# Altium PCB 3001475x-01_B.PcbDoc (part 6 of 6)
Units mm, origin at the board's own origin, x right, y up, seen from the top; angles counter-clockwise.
Board outline 335 x 91 mm, 12 copper layers (Top Layer, L2 GND, Layer 3, L4 GND, Layer 5, L6 PWR, L7 3V3, Layer 8, L9 GND, Layer 10, L11 GND, Bottom Layer), stack 1.59 mm thick; 339 components, 431 nets, 1732 pads, 1526 vias.
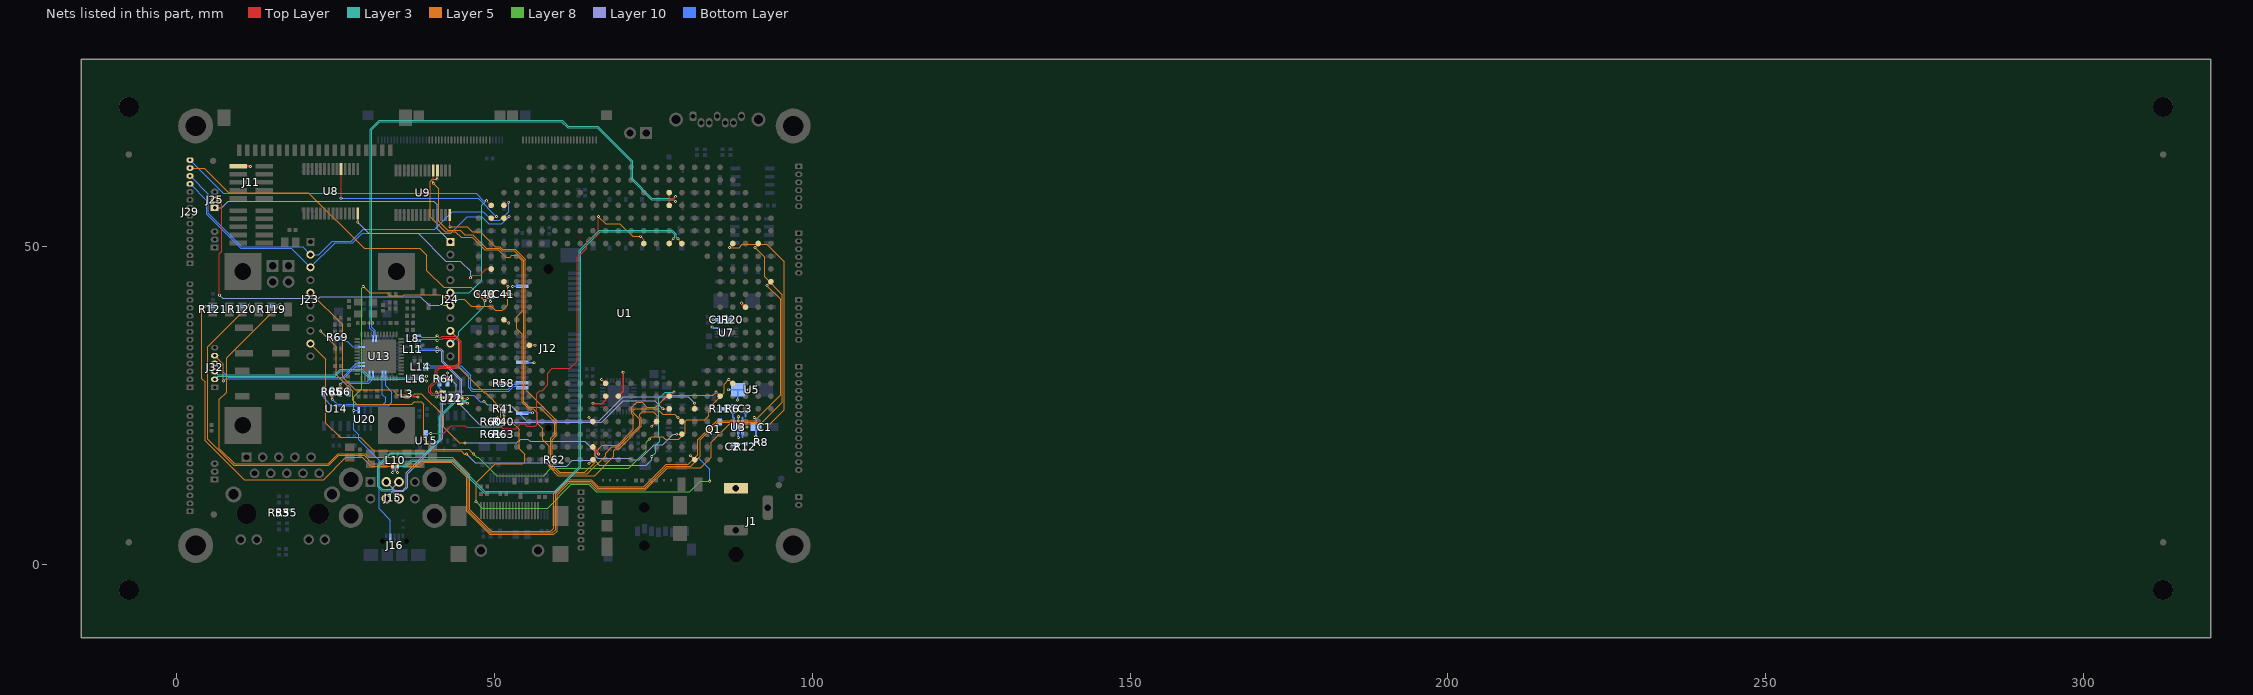
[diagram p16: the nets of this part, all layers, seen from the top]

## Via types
v1: diameter 0.45, hole 0.2, Top Layer to Bottom Layer, 1511 vias
v2: diameter 0.5, hole 0.2, Top Layer to Bottom Layer, 14 vias
v3: diameter 0.45/0.45/0.45/0.45/0.45/0.45/0.45/0.45/0.45/0.45/0.45/0.45 (per signal layer), hole 0.2, Top Layer to Bottom Layer, 1 vias

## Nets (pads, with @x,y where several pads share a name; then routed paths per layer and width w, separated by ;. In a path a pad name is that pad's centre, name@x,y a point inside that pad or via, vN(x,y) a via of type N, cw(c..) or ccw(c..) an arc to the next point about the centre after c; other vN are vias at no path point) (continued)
UART3_RTS_N: U1.AA15 U9.18 | length 88
  Top Layer w0.125: v1(41,60.625) U9.18@41,61.975 ; v1(74.75,21.75) U1.AA15@75.5,22.5
  Layer 5 w0.125: v1(41,60.625) 40.25,60.625 39.875,60.25 39.875,54.75 42.25,52.375 43.875,52.375 44.75,51.5 46.5,51.5 48.5,49.5 50.625,49.5 51.75,48.375 52.5,48.375 52.75,48.625 53.521,48.625 54.375,47.771 54.375,39.875 53.5,39 53.5,37.125 54.375,36.25 54.375,25.521 55.396,24.5 55.604,24.5 56.125,24.5 56.75,23.875 56.75,22.25 57.625,21.375 57.625,19.625 58.625,18.625 58.625,15.375 60,14 65.75,14 68.75,17 68.75,17.875 69.125,18.25 69.625,18.25 73.125,21.75 73.125,23 72.875,23.25 72.875,23.625 73.25,24 75,24 75.625,23.375 75.625,22.625 v1(74.75,21.75)
UART3_RX: U1.AA17 U9.19 | length 89.1
  Top Layer w0.125: v1(40.375,60) U9.19@40.375,62 ; v1(78.875,23.125) U1.AA17@79.5,22.5
  Layer 5 w0.125: v1(40.375,60) 41.25,59.125 41.25,54 42.625,52.625 44.625,52.625 45.375,51.875 46.625,51.875 48.75,49.75 50.75,49.75 51.125,49.375 53.125,49.375 54.625,47.875 54.625,25.625 55.5,24.75 57.125,24.75 59.5,22.375 59.5,20.5 58.875,19.875 58.875,15.5 60.125,14.25 64.625,14.25 67.5,17.125 67.5,17.5 68.5,18.5 69.5,18.5 72.875,21.875 72.875,22.875 71.875,23.875 71.875,24.25 72.125,24.5 75.625,24.5 76.5,23.625 78.375,23.625 v1(78.875,23.125)
UART3_TX: U1.W20 U9.14 | length 86.8
  Top Layer w0.125: U9.14@42.975,55 42.975,53.15 v1(43,53.125) ; U9.14@43,55 U9.14@43,55.025 ; v1(84.875,27.125) U1.W20@85.5,26.5
  Layer 5 w0.125: v1(43,53.125) 45.75,53.125 46.5,52.375 47.75,52.375 50.125,50 50.875,50 51.25,49.625 53.25,49.625 54.875,48 54.875,27.583 59.75,22.708 59.75,20.25 59.125,19.625 59.125,15.625 60.25,14.5 64.25,14.5 65.875,16.125 65.875,17.625 67,18.75 69.375,18.75 71.875,21.25 71.875,23.5 71.625,23.75 71.625,24.75 72.375,25.5 73.25,25.5 74,24.75 75.375,24.75 77.25,26.625 84.375,26.625 v1(84.875,27.125)
UART4_RX: U1.E2 U8.19 | length 31.1
  Top Layer w0.125: v1(25.875,57.625) U8.19@25.875,62.228 ; U1.E2@49.5,54.5 v1(50.325,54.75)
  Bottom Layer w0.125: v1(25.875,57.625) 47.45,57.625 v1(50.325,54.75)
UART4_TX: U1.J2 U8.14 | length 27.2
  Top Layer w0.125: v1(28.5,53.875) U8.14@28.5,55.247 ; v1(46.25,45.125) 46.625,45.5 47.75,45.5 48.75,46.5 U1.J2@49.5,46.5
  Layer 10 w0.125: v1(28.5,53.875) 30.25,52.125 38,52.125 42.375,47.75 44.625,47.75 46.25,46.125 v1(46.25,45.125)
UART5_CTS_N: J24.5 J29.14 U1.D2 | length 68.9
  Top Layer w0.125: v1(48.75,57.25) U1.D2@49.5,56.5
  Layer 3 w0.125: J24.5@43.072,42.758 46.008,42.758 48,44.75 48,56.5 v1(48.75,57.25)
  Bottom Layer w0.125: J29.14@2.125,63.625 7.375,58.375 47.125,58.375 48.25,57.25 v1(48.75,57.25)
UART5_RTS_N: J24.9 J29.13 U1.L2 | length 67.4
  Top Layer w0.125: v1(48.5,41.5) U1.L2@49.5,42.5
  Layer 5 w0.125: J29.13@2.125,62.375 4.375,62.375 8.25,58.5 20.75,58.5 29.5,49.75 38.25,49.75 39.375,48.625 39.375,46.25 42,43.625 46.375,43.625 v1(48.5,41.5)
  Layer 3 w0.125: J24.9@43.072,34.758 44.375,36.061 44.375,36.625 48.5,40.75 v1(48.5,41.5)
  Bottom Layer w0.125: 2,62.875 2,62.625 2.125,62.5 J29.13@2.125,62.375
UART5_RX: J23.2 J29.12 U1.D3 | length 63.3
  Top Layer w0.125: U1.D3@51.5,56.5 v1(52.25,57)
  Bottom Layer w0.125: J29.12@2.125,61.125 5,58.25 5,55.25 10.25,50 19.83,50 J23.2@21.072,48.758 22.367,48.758 24.5,50.891 27.516,50.891 29.375,52.75 40.625,52.75 43.375,55.5 48.25,55.5 49.625,54.125 50.875,54.125 52.25,55.5 v1(52.25,57)
UART5_TX: J23.3 J29.11 U1.E3 | length 61.9
  Top Layer w0.125: U1.E3@51.5,54.5 v1(52.3,54.75)
  Bottom Layer w0.125: J29.11@2.125,59.875 4.75,57.25 4.75,55.125 10.125,49.75 18.08,49.75 J23.3@21.072,46.758 24.939,50.625 27.75,50.625 29.25,52.125 43.125,52.125 45.75,54.75 48,54.75 49.125,53.625 51.175,53.625 v1(52.3,54.75)
USB_HUB_RESET_N: R69.2 U1.V21 U13.26 | length 99.4
  Top Layer w0.125: v1(86.875,29.125) U1.V21@87.5,28.5
  Layer 8 w0.125: v1(46.75,17.375) 47.25,16.875 47.5,16.875 50.375,14 57.771,14 58.896,15.125 71.125,15.125 73.875,17.875 73.875,19.25 v1(74.375,19.75)
  Layer 5 w0.125: v1(22.625,36.75) 25.125,34.25 25.125,29.875 27.75,27.25 27.75,25.875 28.375,25.25 37,25.25 37.375,25.625 38.5,25.625 38.875,25.25 38.875,19.75 40.5,18.125 46,18.125 v1(46.75,17.375) ; v1(74.375,19.75) 74.75,20.125 76.5,20.125 76.875,19.75 79,19.75 80,20.75 80,22.5 80.25,22.75 83.125,22.75 83.75,23.375 83.75,24.625 86.125,27 86.125,28.375 v1(86.875,29.125)
  Bottom Layer w0.125: v1(22.625,36.75) 24.25,35.125 25.25,35.125 25.855,35.73 R69.2@25.855,35.75 26.48,35.125 26.875,35.125 27.75,34.25 U13.26@29.075,34.25
USB_OTG_D_N: L10.1 U1.G16 | length 87
  Top Layer w0.155: v1(34.75,14.5) 34.75,14.923 34.775,14.948 L10.1@34.775,15.525 ; U1.G16@77.5,50.5 v1(78.125,51.25)
  Layer 3 w0.103: v1(34.75,14.5) 34.49,14.76 34.49,15.191 34.745,15.446 36.246,15.446 37.046,16.246 43.429,16.246 48.354,11.321 59.571,11.321 63.575,15.325 63.575,49.325 66.625,52.375 77.876,52.375 78.385,51.866 78.385,51.51 v1(78.125,51.25)
USB_OTG_D_P: L10.4 U1.G17 | length 87.8
  Top Layer w0.155: L10.4@33.975,15.525 33.975,14.948 34,14.923 v1(34,14.5) ; v1(78.875,51.25) U1.G17@79.5,50.5
  Layer 3 w0.103: v1(34,14.5) 34.261,14.76 34.261,15.285 34.65,15.675 36.151,15.675 36.951,16.475 43.524,16.475 48.449,11.55 59.476,11.55 63.346,15.42 63.346,49.42 66.53,52.604 77.971,52.604 78.615,51.96 78.615,51.51 v1(78.875,51.25)
USB_OTG_ID: J16.4 U1.K3 U20.1 | length 72
  Top Layer w0.125: U1.K3@51.5,44.5 v1(52.125,43.75)
  Layer 8 w0.125: v1(27.875,24.25) 27.875,26.375 29.125,27.625 29.125,43.5 v1(29.375,43.75)
  Layer 5 w0.125: v1(29.375,43.75) 30.375,42.75 33.125,42.75 33.625,42.25 35.625,42.25 35.788,42.413 41.837,42.413 42.5,41.75 45.25,41.75 46.375,40.625 49.5,40.625 50.125,40 51.25,40 52.125,40.875 v1(52.125,43.75)
  Bottom Layer w0.125: v1(27.875,24.25) 27.875,21.21 28.625,20.46 28.625,19.625 31.875,16.375 31.875,8.75 33.65,6.975 J16.4@33.65,4.15 ; v1@27.9,24.275 U20.1@28.675,24.275
USB_OTG_OC: R64.1 U1.Y16 U12.2 | length 44.3
  Top Layer w0.125: R64.1@42.625,29.27 v1(42.625,30.125) ; v1(76.5,24.5) U1.Y16@77.5,24.5
  Layer 10 w0.125: v1(42.625,30.125) 42.625,29.625 44,28.25 44,25.75 47.875,21.875 51.25,21.875 51.75,22.375 66.875,22.375 70.25,25.75 75.25,25.75 v1(76.5,24.5)
  Bottom Layer w0.125: U12.2@42.625,28.835 v1(42.625,30.125)
USB_OTG_PWR: U1.Y18 U12.1 | length 46.2
  Top Layer w0.125: U1.Y18@81.5,24.5 v1(81.5,25.375)
  Layer 10 w0.125: v1(48.375,25.625) 48.875,25.125 52.5,25.125 55,22.625 66.5,22.625 70.25,26.375 80.5,26.375 v1(81.5,25.375)
  Bottom Layer w0.125: U12.1@41.345,28.825 41.345,27.78 42.375,26.75 44.25,26.75 44.375,26.625 46.75,26.625 47.75,25.625 v1(48.375,25.625)
USB_OTG_VBUS: U1.G14 U15.D | length 67
  Top Layer w0.125: v1(40,20.625) 42,20.625 43.25,21.875 45.375,21.875 45.625,21.625 51.125,21.625 51.375,21.375 53.375,21.375 54.125,22.125 54.75,22.125 55.125,21.75 56.375,21.75 56.625,22 56.625,26.875 57.125,27.375 57.5,27.375 58.375,28.25 58.375,30.125 59.125,30.875 61.875,30.875 63,32 63,48.25 64.5,49.75 64.5,51 65,51.5 65.75,51.5 66.375,52.125 v1(66.375,54.75) ; v1(73,51.625) 73.5,51.125 U1.G14@73.5,50.5
  Layer 5 w0.125: v1(66.375,54.75) 67.5,53.625 69.75,53.625 71.75,51.625 v1(73,51.625)
  Bottom Layer w0.125: U15.D@39.275,20.625 v1(40,20.625)
USBH1_D_N: J15.A2 L8.2 U21.1 | length 43.3
  Top Layer w0.155: v1@40.757,27.125 v1(40.875,27.125) ; v1(41,36) 41.232,35.768 41.645,35.768 41.778,35.9 43.975,35.9 44.8,35.075 44.8,31.825 43.89,30.915 41.418,30.915 40.975,30.472 40.975,28.875 39.975,27.875 39.975,27.203 40.278,26.9 40.65,26.9 v1(40.875,27.125) ; U21.1@41.775,27.125 v1(40.875,27.125)
  Layer 10 w0.103: J15.A2@33,13 33.896,12.104 33.896,11.804 34.2,11.5 35.7,11.5 36.375,12.175 36.375,14.325 41.9,19.85 41.9,26.434 41.47,26.865 41.136,26.865 v1(40.875,27.125)
  Bottom Layer w0.155: L8.2@37.975,36.025 38.348,36.025 38.606,35.768 40.768,35.768 v1(41,36)
USBH1_D_P: J15.A3 L8.3 U21.2 | length 42
  Top Layer w0.155: v1(41,35.25) 41.232,35.482 41.763,35.482 41.896,35.615 43.857,35.615 44.515,34.957 44.515,31.943 43.772,31.2 41.3,31.2 40.69,30.59 40.69,28.993 39.69,27.993 39.69,27.085 40.16,26.615 40.635,26.615 v1(40.875,26.375) U21.2@41.725,26.375
  Layer 10 w0.103: J15.A3@35,13 34.125,12.125 34.125,11.899 34.295,11.729 35.605,11.729 36.146,12.27 36.146,14.42 41.671,19.945 41.671,26.34 41.375,26.635 41.136,26.635 v1(40.875,26.375)
  Bottom Layer w0.155: L8.3@37.975,35.225 38.325,35.225 38.583,35.482 40.768,35.482 v1(41,35.25)
USBH1_OC_N: R65.1 U13.13 U14.2 | length 15.3
  Top Layer w0.125: v1@24.49,26.01 R65.1@24.49,26.72
  Bottom Layer w0.125: v1@24.49,26.01 U14.2@24.49,27.2 ; v1(24.5,26) 25.25,25.25 32.5,25.25 32.875,25.625 32.875,26.25 32.375,26.75 U13.13@32.375,29.95
USBH1_PWR_EN: U13.12 U14.1 | length 17.2
  Bottom Layer w0.125: U14.1@23.22,27.2 23.22,26.155 24.375,25 33.375,25 33.875,25.5 33.875,27.125 32.875,28.125 U13.12@32.875,29.95
USBH2_D_N: J15.B2 L11.2 U21.5 | length 43
  Top Layer w0.155: U21.5@44.775,26.125 v1(45.75,26.125)
  Layer 10 w0.103: v1(41,34.125) 41.198,33.927 41.572,33.927 41.954,33.545 41.954,31.996 44.854,29.096 44.854,26.22 45.209,25.864 45.49,25.864 v1(45.75,26.125)
  Layer 3 w0.103: J15.B2@33,10.38 33.871,11.251 33.871,11.48 33.73,11.621 32.254,11.621 31.65,12.225 31.65,15.65 33.625,17.625 39.175,17.625 41.292,19.742 41.292,23.292 43.865,25.864 45.49,25.864 v1(45.75,26.125)
  Bottom Layer w0.155: L11.2@37.975,34.275 38.3,34.275 38.6,33.975 40.85,33.975 v1(41,34.125)
USBH2_D_P: J15.B3 L11.3 U21.4 | length 42.6
  Top Layer w0.155: U21.4@44.725,25.375 v1(45.75,25.375)
  Layer 10 w0.103: v1(41,33.5) 41.198,33.698 41.477,33.698 41.725,33.45 41.725,31.901 44.625,29.001 44.625,26.125 45.115,25.635 45.49,25.635 v1(45.75,25.375)
  Layer 3 w0.103: J15.B3@35,10.38 34.1,11.28 34.1,11.575 33.825,11.85 32.349,11.85 31.879,12.32 31.879,15.555 33.72,17.396 39.27,17.396 41.521,19.647 41.521,23.197 43.959,25.635 45.49,25.635 v1(45.75,25.375)
  Bottom Layer w0.155: L11.3@37.975,33.475 38.325,33.475 38.525,33.675 40.825,33.675 v1(41,33.5)
USBH2_OC_N: R66.1 U13.17 U14.3 | length 7.6
  Top Layer w0.125: R66.1@25.76,27.68 v1@25.76,28.365
  Bottom Layer w0.125: U14.3@25.76,27.2 25.76,28.385 26.125,28.75 30,28.75 30.375,29.125 U13.17@30.375,29.95
  other v1: 25.75,28.375
USBH2_PWR_EN: U13.16 U14.4 | length 6
  Bottom Layer w0.125: U14.4@27.03,27.2 27.03,28.155 27.375,28.5 30.25,28.5 30.875,29.125 U13.16@30.875,29.95
USBH3_D_N: J12.36 L14.2 | length 18.3
  Bottom Layer w0.155: L14.2@39.225,31.525 39.575,31.525 39.825,31.275 44.771,31.275 46.255,29.791 46.255,27.922 46.597,27.58 52.155,27.58 52.93,28.355 53.38,28.355 53.625,28.6 J12.36@54.4,28.6
USBH3_D_P: J12.38 L14.3 | length 18.4
  Bottom Layer w0.155: L14.3@39.225,30.725 39.575,30.725 39.845,30.995 44.655,30.995 45.975,29.675 45.975,27.8 46.475,27.3 52.275,27.3 53.05,28.075 53.35,28.075 53.625,27.8 J12.38@54.4,27.8
USBH4_D_N: J32.3 L16.2 | length 35.6
  Layer 3 w0.103: J32.3@6,30.375 6.511,29.864 24.874,29.864 25.76,30.75 29.19,30.75 30.575,29.365 38.99,29.365 39.25,29.625 v1(39.325,29.625)
  Bottom Layer w0.155: L16.2@38.475,29.65 38.475,29.525 39.225,29.525 v1(39.325,29.625)
USBH4_D_P: J32.2 L16.3 | length 35.6
  Layer 3 w0.103: J32.2@6,29.125 6.511,29.635 24.969,29.635 25.855,30.521 29.095,30.521 30.48,29.135 38.99,29.135 39.25,28.875 v1(39.325,28.875)
  Bottom Layer w0.155: L16.3@38.475,28.85 38.475,28.975 39.225,28.975 v1(39.325,28.875)
USBH4_OC_N: J32.4 U13.21 | length 24.9
  Bottom Layer w0.125: J32.4@6,31.625 8.125,29.5 26.125,29.5 28.375,31.75 U13.21@29.075,31.75
USBH4_PWR_EN: J32.5 U13.20 | length 27.3
  Layer 5 w0.125: J32.5@6,32.875 7.375,31.5 v1(7.375,28.875)
  Bottom Layer w0.125: v1(7.375,28.875) 7.75,29.25 26.25,29.25 28.25,31.25 U13.20@29.075,31.25
USBH_D_N: U1.C16 U13.30 | length 90.7
  Top Layer w0.155: U1.C16@77.5,58.5 77.5,57.762 77.623,57.64 78.265,57.64 v1(78.5,57.875)
  Layer 3 w0.103: v1(30.25,38) 30.448,38.198 30.448,68.472 31.851,69.875 60.649,69.875 61.599,68.925 66.274,68.925 71.729,63.47 71.729,60.671 74.785,57.614 78.24,57.614 v1(78.5,57.875)
  Bottom Layer w0.155: v1(30.25,38) 30.425,37.825 30.425,37.204 30.985,36.644 30.985,36.135 30.875,36.025 U13.30@30.875,35.55
USBH_D_P: U1.D16 U13.31 | length 90.3
  Top Layer w0.155: U1.D16@77.5,56.5 77.5,57.238 77.622,57.36 78.265,57.36 v1(78.5,57.125)
  Layer 3 w0.103: v1(30.875,38) 30.677,38.198 30.677,68.377 31.946,69.646 60.554,69.646 61.504,68.696 66.179,68.696 71.5,63.375 71.5,60.576 74.691,57.385 78.24,57.385 v1(78.5,57.125)
  Bottom Layer w0.155: v1(30.875,38) 30.705,37.83 30.705,37.32 31.265,36.76 31.265,36.135 31.375,36.025 U13.31@31.375,35.55
USER_LED0: R121.2 U1.G21 | length 174.4
  Top Layer w0.125: v1(87,49.875) U1.G21@87.5,50.5
  Layer 5 w0.125: v1(4.5,40.625) 4,40.125 4,29.25 4.5,28.75 4.5,19.5 10.625,13.375 23.125,13.375 26.625,16.875 29.25,16.875 30.625,15.5 38.375,15.5 39,16.125 43.25,16.125 45.625,13.75 45.625,8.375 49.25,4.75 59.375,4.75 59.875,5.25 59.875,11 61.75,12.875 65,12.875 66.125,11.75 73.75,11.75 77.25,15.25 82.5,15.25 84.125,16.875 84.125,19.25 87,22.125 93.375,22.125 95.625,24.375 95.625,47.625 92.875,50.375 89,50.375 88.5,49.875 v1(87,49.875)
  Bottom Layer w0.125: v1(4.5,40.625) R121.2@5.73,40.625
USER_LED1: R120.2 U1.G23 | length 167.8
  Top Layer w0.125: v1(91,49.875) U1.G23@91.5,50.5
  Layer 5 w0.125: v1(11.5,40.855) 4.875,34.23 4.875,19.75 9,15.625 23.979,15.625 25.516,17.163 29.5,17.163 30.788,15.875 38.25,15.875 38.875,16.5 43.375,16.5 45.875,14 45.875,8.5 49.375,5 59.125,5 59.625,5.5 59.625,11.125 61.625,13.125 65.125,13.125 66.25,12 73.625,12 77.125,15.5 80.875,15.5 82.375,17 82.375,19.625 85.125,22.375 92.125,22.375 95.288,25.538 95.288,42.462 92.5,45.25 92.5,48.375 v1(91,49.875)
  Bottom Layer w0.125: R120.2@10.375,40.605 10.625,40.855 v1(11.5,40.855)
USER_LED2: R119.2 U1.K24 | length 159.5
  Top Layer w0.125: v1(92.875,43.875) U1.K24@93.5,44.5
  Layer 5 w0.125: v1(16.25,40.875) 7.875,32.5 7.875,27.125 6.75,26 6.75,18.25 9.125,15.875 23.875,15.875 25.413,17.413 29.712,17.413 30.25,16.875 43.375,16.875 46.125,14.125 46.125,8.625 49.5,5.25 58.875,5.25 59.375,5.75 59.375,11.25 61.5,13.375 65.25,13.375 66.375,12.25 73.5,12.25 77,15.75 80.5,15.75 82,17.25 82,19.625 85,22.625 90.958,22.625 95.038,26.704 95.038,41.712 v1(92.875,43.875)
  Bottom Layer w0.125: R119.2@15,40.605 15.27,40.875 v1(16.25,40.875)
VCC_LICELL: R8.2 U1.N3 | length 1.5
  Top Layer w0.125: U1.N3@51.5,38.5 v1(52.25,38)
  Bottom Layer w0.125: v1(90.875,19.25) R8.2@91.52,19.25
VIN: J1.1 Q1.2 R6.1 R11.2 U3.4 U3.8 | length 2.5
  Bottom Layer w0.25: R6.1@87.5,24.02 87.5,23.25 87.725,23.025 U3.4@87.725,22.535 U3.8@87.725,21.625
VLDO3_MCA: J11.1 U1.AC10 U1.M22 | length 4.2
  Top Layer w0.4: J11.1@9.758,62.625 v1(11.625,62.625) ; U1.AC10@65.5,18.5 v1(66.375,17.375) ; v1(88.875,41.125) U1.M22@89.5,40.5
VLDO4_2V5: L3.2 R40.2 R41.2 R53.2 R55.2 R58.2 R60.2 R61.2 R62.2 R63.2 U1.AD10 U1.R5 U1.V3 | length 11.6
  Top Layer w0.125: v1(64.875,15.875) U1.AD10@65.5,16.5
  Top Layer w0.25: L3.2@36.375,26.395 v1@38,26.395 ; v1(50.375,28.5) U1.V3@51.5,28.5 ; U1.R5@55.5,34.5 v1(56.375,34.5)
  Bottom Layer w0.125: v1(15.375,8.625) R53.2@16.105,8.625 ; R55.2@17.395,8.625 v1(18.125,8.625) ; R61.2@49.98,20.5 v1(50.5,21.125) R63.2@51.02,20.5 ; R60.2@49.98,22.5 v1(50.5,23.125) R40.2@51.02,22.5 ; v1(51.5,23.375) R41.2@51.5,24.02 ; R62.2@59.52,16 v1(60.625,16)
  Bottom Layer w0.25: v1(50.375,28.5) R58.2@51.02,28.5
  other v1: 38,26.375
VLDO6_1V5: C40.2 C41.2 J12.6 J12.28 J12.48 U1.AA10 | length 7.4
  Top Layer w0.125: v1(64.875,23.125) U1.AA10@65.5,22.5
  Bottom Layer w0.25: v1(49.375,41.375) C40.2@49.375,42.475 ; C41.2@51.96,42.5 v1(52.625,42.5) ; v1(52.875,43.75) J12.6@54.35,43.75 ; J12.28@54.45,31.75 v1(56.25,31.75) ; J12.48@54.475,23.875 v1(56,23.875)
VSYS: C1.1 C2.2 C3.2 C11.2 R6.2 R12.2 R20.1 U1.V11 U1.W11 U1.W12 U3.1 U3.2 U3.5 U3.6 U3.7 U5.K U7.4 | length 24.3
  Top Layer w0.254: v1(65.5,25.375) 65.602,25.273 66.898,25.273 67.5,25.875 U1.W11@67.5,26.5 ; v1(66.875,29.125) U1.V11@67.5,28.5 ; U1.W12@69.5,26.5 70.25,27.25 v1(70.25,30.25)
  Bottom Layer w0.254: v1(84.25,37.375) 84.45,37.175 U7.4@85,37.175 ; v1(84.375,38.5) C11.2@85.04,38.5 ; v1(86.5,39.125) R20.1@87.02,38.5 ; v1(86.8,27.5) U5.K@88.3,27.5 ; C2.2@87.5,18.96 v2@88.335,18.96 ; R6.2@87.5,24.98 v2@88.48,24.98 ; v2@88.3,25.925 U5.K@88.3,27.5 ; v2@88.375,19.875 v2(88.375,20) U3.2@88.375,20.715 ; U3.5@88.375,22.535 v2(88.375,23.25) ; v2@88.395,18.98 R12.2@89.5,18.98 ; 89.025,20.025 U3.1@89.025,20.715 ; U3.6@89.025,22.535 89.025,23.15 ; 89.5,23.25 C3.2@89.5,24.04 ; v1(90,27.5) U5.K@88.3,27.5 ; v2@91.15,20.15 C1.1@91.15,21.625 91.15,22.975
  other v1: 90.875,23.125
  other v2: 88.375,18.75 91.125,20.125 88.675,21.625 89.75,21.625 88.5,25 88.25,25.875
XBEE_ASSOC: J24.6 J25.2 | length 53.3
  Top Layer w0.125: J25.2@6,57.375 6.875,57.375 7.125,57.125 7.125,49.25 6.75,48.875 v1(6.75,42.375)
  Layer 10 w0.125: v1(6.75,42.375) 7.25,41.875 22.375,41.875 22.625,42.125 38.375,42.125 39.742,40.758 J24.6@43.072,40.758
XBEE_IDENT: J24.1 J25.1 | length 42.3
  Layer 10 w0.125: J25.1@6,56.125 7.125,56.125 8.125,57.125 40.5,57.125 41,56.625 41,52.83 J24.1@43.072,50.758
XBEE_ON/SLEEP_N: J24.8 U1.AD18 | length 84.8
  Top Layer w0.125: v1(80.875,17.125) U1.AD18@81.5,16.5
  Layer 8 w0.125: v1(47.125,9.875) 48.125,8.875 58.375,8.875 62.125,12.625 64.875,12.625 66.038,11.462 80.712,11.462 82.375,13.125 v1(83.875,13.125)
  Layer 5 w0.125: J24.8@43.072,36.758 44.375,35.455 44.375,31 48.375,27 48.625,27 51,24.625 51,23 51.625,22.375 52.75,22.375 53.875,21.25 53.875,18.25 54.75,17.375 54.75,16.125 54.5,15.875 50.125,15.875 47.125,12.875 v1(47.125,9.875)
  Bottom Layer w0.125: v1(80.875,17.125) 81.25,16.75 82.125,16.75 83.875,15 v1(83.875,13.125)
XBEE_RESET_N: J23.5 U1.AB17 | length 77.8
  Top Layer w0.125: v1(78.675,20.5) U1.AB17@79.5,20.5
  Layer 5 w0.125: J23.5@21.072,42.758 26.125,37.705 26.125,29.5 28.125,27.5 34,27.5 34.75,26.75 37.375,26.75 37.5,26.875 38.5,26.875 42,23.375 42,21.625 44.5,19.125 v1(45.375,19.125)
  Layer 10 w0.125: v1(45.375,19.125) 53.5,19.125 54.125,19.75 55.25,19.75 55.625,19.375 64.25,19.375 65.875,17.75 65.875,17.125 66.25,16.75 71.375,16.75 71.625,16.5 72.75,16.5 75.125,18.875 76.5,18.875 78.125,20.5 v1(78.675,20.5)
XBEE_SLEEP_RQ: J23.9 U1.W16 | length 82.6
  Top Layer w0.125: U1.W16@77.5,26.5 v1(78.25,27.125)
  Layer 5 w0.125: J23.9@21.072,34.758 23.5,32.33 23.5,22.25 25.75,20 28.875,20 31,17.875 44.75,17.875 45.25,17.375 v1(45.625,17.375)
  Layer 10 w0.125: v1(45.625,17.375) 47,16 58.25,16 58.75,15.5 61.375,15.5 62.25,16.375 65.75,16.375 66.5,15.625 73.875,15.625 74.75,16.5 v1(74.75,17)
  Layer 3 w0.125: v1(74.75,17) 75.375,17.625 75.375,18.75 76,19.375 76,19.875 75.875,20 75.875,26.125 76.875,27.125 v1(78.25,27.125)
pads on no net: D2.X D3.X FIDUCIAL1.1 FIDUCIAL2.1 FIDUCIAL3.1 FIDUCIAL4.1 FIDUCIAL5.1 FIDUCIAL6.1 H1048.1 H1049.1 H1050.1 H1051.1 H1052.1 H1053.1 H1054.1 H1055.1 J1.3 J1.4 J8.8 J8.9 J10.7 J11.6 J11.7 J11.8 J12.3 J12.5 J12.7 J12.17 J12.19 J12.42 J12.44 J12.45 J12.46 J12.47 J12.49 J12.51 J12.H1 J12.H2 J12.MT1 J12.MT2 J13.MNT1 J13.MNT2 J14.4 J14.8 J14.9 J14.10 J16.10 J16.11 J17.M1 J17.M2 J18.M1 J18.M2 J19.MT1 J19.MT21 J20.M1 J20.M2 J21.M1 J21.M2 J22.4 J22.MT1 J22.MT2 J23.4 J23.6 J23.7 J23.8 J24.2 J24.3 J24.4 J24.7 J24.10 P1.14 P1.H1 P1.H2 U1.A6 U1.A16 U1.A19 U1.A20 U1.AA2 U1.AA11 U1.AA18 U1.AA20 U1.AA21 U1.AA22 U1.AB11 U1.AB13 U1.AB14 U1.AB19 U1.AB20 U1.AB22 U1.AC11 U1.AC14 U1.AC21 U1.AD11 U1.AD12 U1.AD13 U1.AD14 U1.B16 U1.B21 U1.C3 U1.C17 U1.C18 U1.C19 U1.C20 U1.C22 U1.D5 U1.D6 U1.D12 U1.D17 U1.D23 U1.E12 U1.E13 U1.E15 U1.E22 U1.E23 U1.F2 U1.F17 U1.F18 U1.F21 U1.F22 U1.G15 U1.G24 U1.H21 U1.J21 U1.J22 U1.J23 U1.K5 U1.L20 U1.L21 U1.M21 U1.M24 U1.N20 U1.N21 U1.N22 U1.N24 U1.P20 U1.P21 U1.P22 U1.P23 U1.R2 U1.R20 U1.R21 U1.T20 U1.T21 U1.T22 U1.T24 U1.U2 U1.U19 U1.U20 U1.U22 U1.V2 U1.V14 U1.V15 U1.V19 U1.V24 U1.W13 U1.W15 U1.W18 U1.W22 U1.W23 U1.Y2 U1.Y22 U1.Y23 U8.7 U8.8 U8.15 U8.16 U8.20 U8.21 U9.6 U9.7 U9.8 U9.11 U9.15 U9.16 U9.17 U9.20 U9.21 U12.3 U12.5 U13.18 U13.19 U17.8 U17.9 U17.17 U17.19 U17.22 U17.28 U17.30 U18.5 U19.5 U20.2 U20.6 U21.6
copper on no net:
  other v1: 46.125,6.375 80.375,57.875

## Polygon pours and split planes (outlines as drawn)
SHLD on L2 GND "Layer 2 SHLD" (solid, pour order 61): 79.25,3 79.25,1.875 69.25,1.875 69.25,2.875 66.375,2.875 66.375,1.75 62.125,1.75 62.125,9.75 59.125,9.75 59.125,4.125 56.875,4.125 56.875,2.2 46.25,2.25 46.25,13.625 40.375,13.625 40.375,10.125 39.375,10.125 38.125,8.875 38.125,2.875 30.5,2.875 30.5,9.125 29.625,9.125 29.25,9.5 29.25,11.75 27.75,11.75 27.75,13.625 25.5,13.625 25.5,12.375 24.25,12.375 24.25,5.5 24.875,5.5 24.875,1.75 8.75,1.75 8.75,8 10.75,8 10.75,11.75 9.625,12.875 8.25,12.875 7.125,11.75 7.125,10.375 8,9.5 8,0.25 83,0.25 83,3
GND on L2 GND "Layer 2 GND" (solid, pour order 44): 0.5,71.5 99.5,71.5 99.5,0.5 83.5,0.5 83.5,3.5 78.75,3.5 78.75,2.375 69.75,2.375 69.75,3.375 65.875,3.375 65.875,2.25 62.625,2.25 62.625,10.375 58.5,10.375 58.5,4.625 56.375,4.625 56.375,2.75 46.75,2.75 46.75,14 43,14 43,14.5 41.75,15.75 39.375,15.75 38.125,14.5 38.125,10.875 37.625,10.375 37.625,3.375 31,3.375 31,9.625 30.125,9.625 29.75,10 29.75,14.5 28.5,15.75 26.375,15.75 25,14.375 25,12.875 23.75,12.875 22.5,11.625 22.5,9.25 23.75,9.25 23.75,5 24.25,5 24.25,2.25 9.25,2.25 9.277,7.5 11.25,7.5 11.25,12.25 10.125,13.375 7.75,13.375 6.625,12.25 6.625,9.875 7.5,9 7.5,0.5 0.5,0.5
VLDO6_1V5 on L6 PWR "Layer6 VLD06_1V5" (solid, pour order 36): 43.25,39.25 43.25,49.25 64.25,49.25 64.25,24.625 67,24.625 67,21 55.625,21 55.625,32.375 58.125,32.375 58.125,39.25
VSYS on L6 PWR "Layer6 VSYS" (solid, pour order 38): 67.25,21 67.25,24.875 64.5,24.875 64.5,31 83.25,31 83.25,39.625 87.75,39.625 87.75,29 92.125,29 92.125,19.75 90.125,19.75 90.125,17.375 86.375,17.375 86.375,21
NetC72_2 on L6 PWR "Layer 6 NetC72_2" (solid, pour order 37): 26.25,32.875 28.125,32.875 28.125,38.625 30.5,38.625 30.5,36.375 35.125,36.375 35.125,37.125 35.875,37.125 35.875,33.125 36.625,33.125 36.625,32.625 36.375,32.375 34.625,32.375 34.625,28.25 34.875,28.254 34.875,27.625 34,27.625 34,28.625 31,28.625 31,27.625 30.375,27.625 30.375,32.375 26.25,32.375
NetC50_2 on L6 PWR "Layer 6 NetC50_2" (solid, pour order 51): 33.75,37.875 37.125,37.875 37.125,35.125 36.625,35.125 36.625,33.875 37.5,33.875 37.5,30.125 35.625,30.125 35.625,27.5 35.875,27.5 35.875,25.875 28.25,25.875 28.25,28.375 29,28.375 29,27.375 31.25,27.375 31.25,28.375 33.75,28.375 33.75,27.375 35.125,27.375 35.125,28.5 34.875,28.5 34.875,32.125 36.5,32.125 36.875,32.5 36.875,33.375 36.125,33.375 36.125,37.375 34.875,37.375 34.875,36.625 33.75,36.625
NetC42_2 on L6 PWR "Layer 6 NetC42_2" (solid, pour order 53): 27.25,29.375 27.25,31.75 25.25,31.75 25.25,33.5 27.25,33.5 27.25,34.75 26.125,34.75 26.125,38.625 27.875,38.625 27.875,33.125 26,33.125 26,32.125 30.125,32.125 30.125,29.375
NetC46_2 on L6 PWR "Layer 6 NetC46_2" (solid, pour order 54): 33.5,36.625 33.5,38.125 37.375,38.125 37.375,34.875 36.875,34.875 36.875,34.125 37.75,34.125 37.75,29.875 35.875,29.875 35.875,27.75 36.125,27.75 36.125,25.625 28,25.625 28,28.625 29.25,28.625 29.25,27.625 30.125,27.625 30.125,29.125 27.25,29.125 27.25,28.25 25.875,28.25 25.875,25 37.5,25 37.5,29 43,29 43,38.625 30.75,38.625 30.75,36.625
RGMII_1V2 on L6 PWR "Layer 6 RGMII_1V2" (solid, pour order 50): 42.875,38.875 42.875,49 21.25,49 21.25,25 25.625,25 25.625,28.5 27,28.5 27,31.5 25,31.5 25,33.75 27,33.75 27,34.5 25.875,34.5 25.875,38.875
SHLD on L6 PWR "Layer 6 SHLD" (solid, pour order 57): 79.25,3 79.25,1.875 69.25,1.875 69.25,2.875 66.375,2.875 66.375,1.75 62.125,1.75 62.125,9.75 59.125,9.75 59.125,4.125 56.875,4.125 56.875,2.2 46.25,2.25 46.25,13.625 40.375,13.625 40.375,10.125 39.375,10.125 38.125,8.875 38.125,2.875 30.5,2.875 30.5,9.125 29.625,9.125 29.25,9.5 29.25,11.75 27.75,11.75 27.75,13.625 24.25,13.625 24.25,5.5 24.875,5.5 24.875,1.75 8.75,1.75 8.75,8 10.75,8 10.75,11.75 9.625,12.875 8.25,12.875 7.125,11.75 7.125,10.375 8,9.5 8,0.25 83,0.25 83,3
VLDO4_2V5 on L6 PWR "Layer6 VLD04_2V5" (solid, pour order 34): 15,8 18.75,8 18.75,20.5 30.25,20.5 30.25,17.375 41.875,17.375 41.875,22.875 48.5,22.875 48.5,17.5 49.5,17.5 49.5,15.125 65.5,15.125 65.5,19 53.5,19 53.5,33.875 56.75,33.875 56.75,37.25 51.5,37.25 51.5,39 43.25,39 43.25,28.75 37.75,28.75 37.75,18.75 31.5,18.75 31.5,24.75 15,24.75
VCC_LICELL on L6 PWR "Layer 6 NetC46_2" (solid, pour order 52): 53.75,19.25 53.75,33.625 57.125,33.625 57.125,37.5 51.75,37.5 51.75,39 57.875,39 57.875,32.625 55.375,32.625 55.375,20.75 86.125,20.75 86.125,17.125 90.375,17.125 90.375,19.5 91.625,19.5 91.625,16.375 84.75,16.375 84.75,19.625 65.5,19.625 65.5,19.25
VLDO3_MCA on L6 PWR "Layer 6 NetC46_2" (solid, pour order 55): 65.75,19.375 84.5,19.375 84.5,16.125 91.875,16.125 91.875,19.5 92.375,19.5 92.375,29.25 88,29.25 88,39.875 83.25,39.875 83.25,50.25 64.25,50.25 64.25,49.5 43,49.5 43,49.25 21.25,49.25 21.25,51 10.625,51 10.625,63 15.625,63 15.625,53 62.625,53 62.625,52 86.375,52 86.375,41.875 89.875,41.875 89.875,30.875 94,30.875 94,14.25 65.75,14.25
5V on L6 PWR "Layer6 5V" (solid, pour order 33): 1,6.75 7.5,6.75 7.5,9 6.625,9.875 6.625,12.25 7.75,13.375 14.75,13.375 14.75,25 21,25 21,50.75 10.375,50.75 10.375,63.25 15.875,63.25 15.875,53.25 62.875,53.25 62.875,52.25 86.625,52.25 86.625,42.125 90.125,42.125 90.125,31.125 94.25,31.125 94.25,14 65.5,14 65.5,14.875 49.25,14.875 49.25,17.25 48.25,17.25 48.25,22.625 42.125,22.625 42.125,17.125 30,17.125 30,20.25 19,20.25 19,7.625 14.75,7.625 14.75,13.375 11.125,13.375 11.125,7.5 9.25,7.5 9.25,2.25 24.25,2.25 24.25,5 23.75,5 23.75,8 22.5,8 22.5,11.625 23.75,12.875 25,12.875 25,14.375 26.375,15.75 28.5,15.75 29.75,14.5 29.75,9.625 31,9.625 31,3.375 37.625,3.375 37.625,14 39.375,15.75 41.75,15.75 43,14.5 43,14.125 46.75,14.125 46.75,2.75 56.375,2.75 56.375,4.625 58.625,4.625 58.625,10.125 62.625,10.125 62.625,3.125 65.875,3.125 65.875,3.375 69.75,3.375 69.75,2.375 78.75,2.375 78.75,3.5 83.5,3.5 83.5,1 99,1 99,71 1,71
SHLD on Top Layer "Layer 1 SHLD" (solid, pour order 56): 8.75,1.75 8.75,8 10.718,8 10.718,11.048 ccw(c8.968,11.048) 7.964,9.614 7.964,0.25 83,0.25 83,3 79.25,3 79.25,1.875 69,1.875 69,1 66.5,1 66.5,1.75 62.125,1.75 62.125,9.75 59.125,9.75 59.125,4.125 56.875,4.125 56.875,2.25 46.25,2.25 46.25,13.625 42.25,13.625 42.25,12 41.875,11.625 40.375,11.625 40.375,10.17 40.57,10.17 ccw(c40.57,7.67) 38.07,7.67 38.07,2.875 30.5,2.875 30.5,9.125 29.625,9.125 29.25,9.5 29.25,11.75 25.75,11.75 25.75,10.25 25,9.625 24.25,9.625 24.25,5.5 24.75,5.5 24.75,1.75
VIN on Bottom Layer "Layer 12 VIN" (solid, pour order 35): 85.125,10.5 85.125,21.375 84.25,21.375 84.25,23.875 85.625,23.875 85.625,24.875 86.875,24.875 86.875,24.375 87.75,24.375 87.75,21.375 86.5,21.375 86.5,19.5 86.875,19.5 86.875,16.875 89.875,16.875 90.625,16.125 90.625,10.5
SHLD on Bottom Layer "Layer 12 SHLD" (solid, pour order 58): 79.25,3 79.25,1.875 69.25,1.875 69.25,2.875 66.375,2.875 66.375,1.75 62.125,1.75 62.125,9.75 59.125,9.75 59.125,4.125 56.875,4.125 56.875,2.2 46.25,2.25 46.25,13.625 40.375,13.625 40.375,10.125 39.375,10.125 38.125,8.875 38.125,2.875 30.5,2.875 30.5,9.125 29.625,9.125 29.25,9.5 29.25,11.75 27.75,11.75 27.75,13.625 24.25,13.625 24.25,5.5 24.875,5.5 24.875,1.75 8.75,1.75 8.75,8 10.75,8 10.75,11.75 9.625,12.875 8.25,12.875 7.125,11.75 7.125,10.375 8,9.5 8,0.25 83,0.25 83,3
GND on L11 GND "Layer 11 GND" (solid, pour order 39): 0.5,71.5 99.5,71.5 99.5,0.5 83.5,0.5 83.5,3.5 78.75,3.5 78.75,2.375 69.75,2.375 69.75,3.375 65.875,3.375 65.875,2.25 62.625,2.25 62.625,10.375 58.5,10.375 58.5,4.625 56.375,4.625 56.375,2.75 46.75,2.75 46.75,14 43,14 43,14.5 41.75,15.75 39.375,15.75 38.125,14.5 38.125,10.875 37.625,10.375 37.625,3.375 31,3.375 31,9.625 30.125,9.625 29.75,10 29.75,14.5 28.5,15.75 26.375,15.75 25,14.375 25,12.875 23.75,12.875 22.5,11.625 22.5,9.25 23.75,9.25 23.75,5 24.25,5 24.25,2.25 9.25,2.25 9.277,7.5 11.25,7.5 11.25,12.25 10.125,13.375 7.75,13.375 6.625,12.25 6.625,9.875 7.5,9 7.5,0.5 0.5,0.5
SHLD on L11 GND "Layer 11 SHLD" (solid, pour order 59): 79.25,3 79.25,1.875 69.25,1.875 69.25,2.875 66.375,2.875 66.375,1.75 62.125,1.75 62.125,9.75 59.125,9.75 59.125,4.125 56.875,4.125 56.875,2.2 46.25,2.25 46.25,13.625 40.375,13.625 40.375,10.125 39.375,10.125 38.125,8.875 38.125,2.875 30.5,2.875 30.5,9.125 29.625,9.125 29.25,9.5 29.25,11.75 27.75,11.75 27.75,13.625 25.5,13.625 25.5,12.375 24.25,12.375 24.25,5.5 24.875,5.5 24.875,1.75 8.75,1.75 8.75,8 10.75,8 10.75,11.75 9.625,12.875 8.25,12.875 7.125,11.75 7.125,10.375 8,9.5 8,0.25 83,0.25 83,3
GND on L9 GND "Layer 9 GND" (solid, pour order 41): 0.5,71.5 99.5,71.5 99.5,0.5 83.5,0.5 83.5,3.5 78.75,3.5 78.75,2.375 69.75,2.375 69.75,3.375 65.875,3.375 65.875,2.25 62.625,2.25 62.625,10.375 58.5,10.375 58.5,4.625 56.375,4.625 56.375,2.75 46.75,2.75 46.75,14 43,14 43,14.5 41.75,15.75 39.375,15.75 38.125,14.5 38.125,10.875 37.625,10.375 37.625,3.375 31,3.375 31,9.625 30.125,9.625 29.75,10 29.75,14.5 28.5,15.75 26.375,15.75 25,14.375 25,12.875 23.75,12.875 22.5,11.625 22.5,9.25 23.75,9.25 23.75,5 24.25,5 24.25,2.25 9.25,2.25 9.277,7.5 11.25,7.5 11.25,12.25 10.125,13.375 7.75,13.375 6.625,12.25 6.625,9.875 7.5,9 7.5,0.5 0.5,0.5
SHLD on L9 GND "Layer 9 SHLD" (solid, pour order 60): 79.25,3 79.25,1.875 69.25,1.875 69.25,2.875 66.375,2.875 66.375,1.75 62.125,1.75 62.125,9.75 59.125,9.75 59.125,4.125 56.875,4.125 56.875,2.2 46.25,2.25 46.25,13.625 40.375,13.625 40.375,10.125 39.375,10.125 38.125,8.875 38.125,2.875 30.5,2.875 30.5,9.125 29.625,9.125 29.25,9.5 29.25,11.75 27.75,11.75 27.75,13.625 25.5,13.625 25.5,12.375 24.25,12.375 24.25,5.5 24.875,5.5 24.875,1.75 8.75,1.75 8.75,8 10.75,8 10.75,11.75 9.625,12.875 8.25,12.875 7.125,11.75 7.125,10.375 8,9.5 8,0.25 83,0.25 83,3
3V3 on L7 3V3 "Layer 7 3V3" (solid, pour order 40): 0.5,71.5 99.5,71.5 99.5,0.5 83.5,0.5 83.5,3.5 78.75,3.5 78.75,2.375 69.75,2.375 69.75,3.375 65.875,3.375 65.875,2.25 62.625,2.25 62.625,10.375 58.5,10.375 58.5,4.625 56.375,4.625 56.375,2.75 46.75,2.75 46.75,14 43,14 43,14.5 41.75,15.75 39.375,15.75 38.125,14.5 38.125,10.875 37.625,10.375 37.625,3.375 31,3.375 31,9.625 30.125,9.625 29.75,10 29.75,14.5 28.5,15.75 26.375,15.75 25,14.375 25,12.875 23.75,12.875 22.5,11.625 22.5,9.25 23.75,9.25 23.75,5 24.25,5 24.25,2.25 9.25,2.25 9.277,7.5 11.25,7.5 11.25,12.25 10.125,13.375 7.75,13.375 6.625,12.25 6.625,9.875 7.5,9 7.5,0.5 0.5,0.5
SHLD on L7 3V3 "Layer 7 SHLD" (solid, pour order 63): 79.25,3 79.25,1.875 69.25,1.875 69.25,2.875 66.375,2.875 66.375,1.75 62.125,1.75 62.125,9.75 59.125,9.75 59.125,4.125 56.875,4.125 56.875,2.2 46.25,2.25 46.25,13.625 40.375,13.625 40.375,10.125 39.375,10.125 38.125,8.875 38.125,2.875 30.5,2.875 30.5,9.125 29.625,9.125 29.25,9.5 29.25,11.75 27.75,11.75 27.75,13.625 25.5,13.625 25.5,12.375 24.25,12.375 24.25,5.5 24.875,5.5 24.875,1.75 8.75,1.75 8.75,8 10.75,8 10.75,11.75 9.625,12.875 8.25,12.875 7.125,11.75 7.125,10.375 8,9.5 8,0.25 83,0.25 83,3
SHLD on L4 GND "Layer 4 SHLD" (solid, pour order 62): 79.25,2.9 79.25,1.775 69.25,1.775 69.25,2.775 66.375,2.775 66.375,1.65 62.125,1.65 62.125,9.65 59.125,9.65 59.125,4.025 56.875,4.025 56.875,2.1 46.25,2.15 46.25,13.525 40.375,13.525 40.375,10.025 39.375,10.025 38.125,8.775 38.125,2.775 30.5,2.775 30.5,9.025 29.625,9.025 29.25,9.4 29.25,11.65 27.75,11.65 27.75,13.525 25.5,13.525 25.5,12.275 24.25,12.275 24.25,5.4 24.875,5.4 24.875,1.65 8.75,1.65 8.75,7.9 10.75,7.9 10.75,11.65 9.625,12.775 8.25,12.775 7.125,11.65 7.125,10.275 8,9.4 8,0.15 83,0.15 83,2.9
GND on L4 GND "Layer 4 GND" (solid, pour order 49): 0.5,71.5 99.5,71.5 99.5,0.5 83.5,0.5 83.5,3.5 78.75,3.5 78.75,2.375 69.75,2.375 69.75,3.25 66.25,3.25 66.25,4.25 69.25,4.25 69.25,9.875 77.5,9.875 77.5,13.875 74.25,13.875 74.25,12.875 71.125,12.875 71.125,13.375 71.5,13.375 71.5,17.5 72.25,17.5 72.25,16.875 73.625,16.875 73.625,19.25 72.875,19.25 72.875,20 73.75,20 73.75,23.875 74.875,23.875 74.875,25.25 75.875,25.25 75.875,27.625 73.25,27.625 73.25,26.875 71.25,26.875 71.25,23.625 66.5,23.625 66.5,24.25 65.25,24.25 65.25,20.25 69.25,20.25 69.25,17.5 67.625,17.5 67.625,13.25 66.25,13.25 66.25,3.25 65.875,3.25 65.875,2.25 62.625,2.25 62.625,10.375 58.5,10.375 58.5,4.625 56.375,4.625 56.375,2.75 46.75,2.75 46.75,14 43,14 43,14.5 41.75,15.75 39.375,15.75 38.125,14.5 38.125,10.875 37.625,10.375 37.625,3.375 31,3.375 31,9.625 30.125,9.625 29.75,10 29.75,14.5 28.5,15.75 26.375,15.75 25,14.375 25,12.875 23.75,12.875 22.5,11.625 22.5,9.25 23.75,9.25 23.75,5 24.25,5 24.25,2.25 9.25,2.25 9.277,7.5 11.25,7.5 11.25,12.25 10.125,13.375 7.75,13.375 6.625,12.25 6.625,9.875 7.5,9 7.5,0.5 0.5,0.5
AGND on L4 GND "Layer 4 AGND" (solid, pour order 64): 72.5,17.125 73.375,17.125 73.375,19 73.25,19 72.625,19 72.625,20.25 73.375,20.25 73.375,24.125 74.5,24.125 74.625,24.125 74.625,25.5 75.625,25.5 75.625,27.375 73.5,27.375 73.5,26.625 71.5,26.625 71.5,23.375 66.25,23.375 66.25,24 65.5,24 65.5,24.125 65.5,20.5 65.625,20.5 69.5,20.5 69.5,20.25 69.5,17.25 67.875,17.25 67.875,17.125 67.875,13 68,13 66.5,13 66.5,12.125 66.5,4.5 69,4.5 69,10.125 77.25,10.125 77.25,13.625 77.375,13.625 74.5,13.625 74.5,12.625 71.25,12.625 71.25,12.875 71.25,17.75 71.625,17.75 72.5,17.75

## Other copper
Top Layer:
  pour cut-out: 65,49.5 65,31.75 82.5,31.75 82.5,49.5
  text "REV B" at 40.3,44.75 h0.63 r90
  text "30014752-01_TOP" at 39.25,43.912 h0.63 r90
  text "CCIMX6_SBC" at 24,21.5 h0.75
  text ".Layer_Name" at 41.25,-18.875 h2.54
L7 3V3:
  pour cut-out: 64.25,50.25 64.25,31 83.25,31 83.25,50.25
  text ".Layer_Name" at 44.75,-19.25 h2.54
Layer 8:
  pour cut-out: 82.5,31.75 82.5,49.5 65,49.5 65,31.75
  text ".Layer_Name" at 41.047,-19 h2.54
Layer 5:
  pour cut-out: 82.5,49.5 65,49.5 65,31.75 82.5,31.75
  text ".Layer_Name" at 42.625,-19 h2.54
Layer 10:
  pour cut-out: 65,31.75 82.5,31.75 82.5,49.5 65,49.5
  text ".Layer_Name" at 41.25,-18.875 h2.54
L6 PWR:
  text ".Layer_Name" at 44.125,-19.375 h2.54
Layer 3:
  pour cut-out: 65,49.5 65,31.75 82.5,31.75 82.5,49.5
  text ".Layer_Name" at 42.5,-19 h2.54
L9 GND:
  pour cut-out: 65,49.5 65,31.75 82.5,31.75 82.5,49.5
  text ".Layer_Name" at 43.5,-19 h2.54
L11 GND:
  pour cut-out: 65,49.5 65,31.75 82.5,31.75 82.5,49.5
  text ".Layer_Name" at 43.375,-19.25 h2.54
L2 GND:
  pour cut-out: 65,49.5 65,31.75 82.5,31.75 82.5,49.5
  text ".Layer_Name" at 43.75,-19.125 h2.54
L4 GND:
  pour cut-out: 65,49.5 65,31.75 82.5,31.75 82.5,49.5
  text ".Layer_Name" at 44,-19.375 h2.54
Bottom Layer:
  region net VSYS: 88,23 88,25.5 87.25,25.5 87.25,26.25 89.625,26.25 89.625,27.75 90.5,27.75 90.5,25.5 89,25.5 89,23.5 91.375,23.5 91.375,22.625 90,22.625 90,20.75 91.375,20.75 91.375,19.75 88.75,19.75 88.75,18.625 88,18.625 88,20.25 89.5,20.25 89.5,23
  region net GND: 85.625,37.375 85.625,37.875 87.375,37.875 87.375,37.375 86.625,37.375 86.625,35.625 87.375,35.625 87.375,35.125 85.625,35.125 85.625,35.625 86.375,35.625 86.375,37.375
  pour cut-out: 82.5,49.5 65,49.5 65,31.75 82.5,31.75
  text "CCIMX6_SBC" at 17,32.875 h0.75
  text "30014752-01_BOT" at 18.625,31.5 h0.75
  text "REV B" at 13.75,30.3 h0.75
  text ".Layer_Name" at 37.526,-19 h2.54

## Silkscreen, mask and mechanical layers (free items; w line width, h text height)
Top Overlay:
  drawing of 2583 lines, arcs and shapes, not listed
  text "1" at 67.5,66.125 h0.4
  text "1" at 51.125,65.75 h0.4
  text "CSI" at 51.5,65.75 h0.75
  text "1" at 81.25,65.25 h0.4
  text "SATA" at 78,65.125 h0.75
  text "1" at 74.375,64.875 h0.4 r90
  text "1" at 34.375,64.25 h0.4
  text "CSI0" at 37.625,64.25 h0.75
  text "LVDS0" at 29.5,63.25 h0.75
  text "UART" at 3.625,63.125 h0.75 r270
  text "1" at 7.75,62.625 h0.4
  text "1" at 96.125,62.375 h0.4
  text "XBee" at 5.125,60.5 h0.75
  text "SWD" at 15.625,58.25 h0.75
  text "1" at 8.75,56.25 h0.4 r90
  text "1" at 7.5,55.677 h0.4
  text "CAN" at 96.5,55.375 h0.75 r90
  text "JTAG" at 15.875,53.5 h0.75
  text "1" at 96.125,52.5 h0.4
  text "1" at 7.5,49.625 h0.4 r270
  text "1" at 13.75,48.25 h0.4
  text "1" at 19.125,47.5 h0.4
  text "Cons" at 4.25,47.375 h0.75
  text "1" at 3.75,47 h0.4 r270
  text "XBEE" at 26,44.75 h1
  text "I2C" at 96.5,44 h0.75 r90
  text "LVDS1" at 3.625,43.25 h0.75 r270
  text "MODULE" at 24.75,43.125 h1
  text "USER0" at 5.75,42 h0.75
  text "USER1" at 10.375,42 h0.75
  text "USER2" at 15,42 h0.75
  text "1" at 96.125,41.375 h0.4
  text "USB" at 4.25,36.125 h0.75
  text "SW1" at 9.875,34.5 h0.75 r90
  text "SPI" at 96.5,34.125 h0.75 r90
  text "Power" at 8.75,34 h0.75 r90
  text "1" at 96.125,30.875 h0.4
  text "1" at 3.5,27.625 h0.4
  text "SW2" at 9.75,27.625 h0.75 r90
  text "Reset" at 8.5,27.25 h0.75 r90
  text "1" at 7.5,26.5 h0.4
  text "GPIO" at 3.75,21.5 h0.75 r270
  text "GIGABIT" at 14.875,20.625 h0.75
  text "ETHERNET" at 14.625,19.5 h0.75
  text "1" at 8.125,17.875 h0.4
  text "PWR" at 4.625,17.625 h0.75
  text "for iMX6 SBC" at 44.625,15.25 h0.75 r90
  text "CONNECT CORE" at 43.25,14.875 h0.75 r90
  text "AUDIO" at 62.875,13.25 h0.75
  text "PWR" at 83.5,13.125 h0.75
  text "5VDC@3A" at 86.75,13.125 h0.75
  text "CSI1" at 96.5,13.125 h0.75 r90
  text "1" at 7.5,13 h0.4
  text "1" at 97,12.375 h0.4 r90
  text "1" at 61.75,11.625 h0.4
  text "HDMI" at 46.375,9.875 h0.75 r90
  text "USB" at 42.5,9.625 h0.75 r90
  text "1" at 57.625,9.125 h0.4
  text "1" at 3.5,7.625 h0.4
  text "COINCELL" at 96.375,7.25 h0.75 r90
  text "3VDC@1uA" at 95.25,5.625 h0.75 r90
  text "HEADPHONE" at 81.625,4.625 h0.75 r90
  text ".Layer_Name" at 36.905,-19.012 h2.54
Bottom Overlay:
  drawing of 2575 lines, arcs and shapes, not listed
  text "1" at 54.875,65.625 h0.5
  text "1" at 30.125,65.25 h0.5
  text "LCD" at 34,64.375 h0.75
  text "MIPI DSI" at 62,64.25 h0.75
  text "1" at 63.375,47 h0.4 r90
  text "PCI EXPRESS MINI CARD" at 64.625,46.875 h0.75 r90
  text "MICRO SD" at 82.875,12 h0.75 r90
  text "1" at 37,5.5 h0.5
  text "USB OTG" at 44,3.5 h0.75
  text ".Layer_Name" at 36.742,-18.873 h2.54
Top Paste:
  text ".Layer_Name" at 39.548,-18.889 h2.54
Bottom Paste:
  text ".Layer_Name" at 37.409,-19.018 h2.54
Top Solder:
  text ".Layer_Name" at 38.026,-18.881 h2.54
Bottom Solder:
  text ".Layer_Name" at 37.014,-19.018 h2.54
Panel Outline:
  lines w0.25: 192.5,74.5 215,74.5 cw(c215,73.25) 215,72 205,72 205,62 cw(c203.75,62) 202.5,62 202.5,72 192.54,72 cw(c192.54,73.25) 192.54,74.5 ; 287.5,72 222.5,72 cw(c222.5,73.25) 222.5,74.5 287.5,74.5 ; 287.58,72 ccw(c287.58,73.25) 287.58,74.5 ; 295,72 305,72 305,62 ccw(c306.25,62) 307.5,62 307.5,72 ccw(c305,72) 305,74.5 295,74.5 ; 295.08,72 cw(c295.08,73.25) 295.08,74.5 ; -15,-11.5 320,-11.5 320,79.5 -15,79.5 -15,-11.5 ; -2.5,-2.75 ccw(c-1.25,-2.75) -1.25,-4 60.975,-4 ccw(c60.975,-2.75) 62.225,-2.75 62.225,-1.25 ccw(c60.975,-1.25) 60.975,0 0,0 0,10 ccw(c-1.25,10) -2.5,10 -2.5,-2.75 ; -2.5,17.5 ccw(c-1.25,17.5) 0,17.5 0,54.5 ccw(c-1.25,54.5) -2.5,54.5 -2.5,17.5 ; -2.5,62 ccw(c-1.25,62) 0,62 0,72 10,72 ccw(c10,73.25) 10,74.5 0,74.5 ccw(c0,72) -2.5,72 -2.5,62 ; 17.5,72 cw(c17.5,73.25) 17.5,74.5 82.5,74.5 cw(c82.5,73.25) 82.5,72 17.5,72 ; 65.5,32.25 82,32.25 82,49 65.5,49 65.5,32.25 ; 66.225,-2.75 ccw(c67.475,-2.75) 67.475,-4 93,-4 163.475,-4 ccw(c163.475,-2.75) 164.725,-2.75 164.725,-1.25 ccw(c163.475,-1.25) 163.475,0 102.5,0 102.5,10 ccw(c101.25,10) 100,10 100,0 67.475,0 ccw(c67.475,-1.25) 66.225,-1.25 66.225,-2.75 ; 90,72 cw(c90,73.25) 90,74.5 112.54,74.5 cw(c112.54,73.25) 112.54,72 102.5,72 102.5,62 cw(c101.25,62) 100,62 100,72 90,72 ; 100,16.25 ccw(c101.25,16.25) 102.5,16.25 102.5,54.5 ccw(c101.25,54.5) 100,54.5 100,16.25 ; 120,72 cw(c120,73.25) 120,74.5 185,74.5 cw(c185,73.25) 185,72 120,72 ; 168.725,-2.75 ccw(c169.975,-2.75) 169.975,-4 266.05,-4 ccw(c266.05,-2.75) 267.3,-2.75 267.3,-1.25 ccw(c266.05,-1.25) 266.05,0 205,0 205,10 ccw(c203.75,10) 202.5,10 202.5,0 169.975,0 ccw(c169.975,-1.25) 168.725,-1.25 168.725,-2.75 ; 202.5,16.25 ccw(c203.75,16.25) 205,16.25 205,54.5 ccw(c203.75,54.5) 202.5,54.5 202.5,16.25 ; 271.3,-2.75 ccw(c272.55,-2.75) 272.55,-4 306.25,-4 ccw(c306.25,-2.75) 307.5,-2.75 307.5,10 ccw(c306.25,10) 305,10 305,0 272.55,0 ccw(c272.55,-1.25) 271.3,-1.25 271.3,-2.75 ; 305,16.25 ccw(c306.25,16.25) 307.5,16.25 307.5,54.5 ccw(c306.25,54.5) 305,54.5 305,16.25
Top Assembly:
  text ".Layer_Name" at 35.875,-18.875 h2.54
Bottom Assembly:
  text ".Layer_Name" at 70.324,-19.016 h2.54
Board Outline:
  lines w0.25: 0,0 100,0 100,72 0,72 0,0
PCB Name:
  text "CCIMX6_SBC_0.1" at 36.25,-24.125 h2.54
Sheet Graphics:
  drawing of 2178 lines, arcs and shapes, not listed
  text "1" at -26.517,248.824 h1.78
  text "2" at 74.956,248.824 h1.78
  text "3" at 176.429,248.824 h1.78
  text "4" at 278.054,248.824 h1.78
  text "5" at 379.612,248.824 h1.78
  text "6" at 481.17,248.824 h1.78
  text "7" at 582.812,248.824 h1.78
  text "8" at 684.285,248.824 h1.78
  text "NOTES:" at 349.935,228.685 h5.08
  text "L1 -TOP SIDE IMPEDANCE CONTROLLED SIGNAL .051 Cu FINISHED" at 56.701,228.181 h2.07
  text "1-106 & 1-1080 = .132mm" at -33.625,224.25 h2.07
  text "L2 - GND .015 Cu" at 56.701,219.894 h2.07
  text "1. Manufacture in accordance with IPC-A-600, class 2 & IPC-6012," at 349.935,219.16 h5.08
  text "1-1080/106 Core = .104mm" at -36.5,216 h2.07
  text "L3 - IMPEDANCE CONTROLLED SIGNAL .015 Cu" at 56.701,211.606 h2.07
  text "class 2 the latest standards." at 365.175,209 h5.08
  text "2-1080 = .141mm" at -17.888,207.462 h2.07
  text "L4 - GND .015 Cu" at 56.701,203.319 h2.07
  text "1-1080/106 Core = .104mm" at -36.5,199.2 h2.07
  text "2. Manufacturing process and materials used must comply with ROHS directive" at 349.935,198.84 h5.08
  text "L5- SIGNAL .015 Cu" at 56.701,195.031 h2.07
  text "2-1080 = .141mm" at -17.888,190.887 h2.07
  text "2002/95/EC." at 365.175,188.68 h5.08
  text "A" at -73.685,187.915 h1.78
  text "A" at 731.495,187.915 h1.78
  text "L6 - SPLIT POWER .015 Cu" at 56.701,186.743 h2.07
  text "1-1080/106 Core = .104mm" at -36.5,182.9 h2.07
  text "3. Material: 370HR" at 349.935,178.52 h5.08
  text "L7 - 3V PWR .015 Cu" at 56.701,178.456 h2.07
  text "2-1080 = .141mm" at -17.888,174.312 h2.07
  text "L8 - IMPEDANCE CONTROLLED SIGNAL .015 Cu" at 56.701,170.168 h2.07
  text "Laminate and prepreg shall be per IPC-4101/126." at 365.175,168.36 h5.08
  text "1-1080/106 Core = .104mm" at -36.1,166.25 h2.07
  text "L9 - GND .015 Cu" at 56.701,161.881 h2.07
  text "4. The original Gerber data must be increased to account for manufacturing" at 349.935,158.2 h5.08
  text "2-1080 = .141mm" at -17.888,157.737 h2.07
  text "L10 - IMPEDANCE CONTROLLED SIGNAL .015 Cu" at 56.701,153.593 h2.07
  text "1-1080/106 Core = .104mm" at -36.775,149.95 h2.07
  text "etch tolerances.  Nominal track width +/-10% is expected." at 365.175,148.04 h5.08
  text "L11 - GND .015 Cu" at 56.701,145.305 h2.07
  text "1-106 & 1-1080 = .132mm" at -33.625,141.25 h2.07
  text "5. Apply E.N.I.G. to all exposed copper per IPC-4552." at 349.935,137.88 h5.08
  text "BOTTOM SIDE - IMPEDANCE CONTROLLED SIGNAL .051 Cu FINISHED" at 56.701,137.018 h2.07
  text "6. Starting copper weight is 1/2 oz. for all layers." at 349.935,127.72 h5.08
  text "7. Prepreg height and dielectric constant are critical items." at 349.935,117.56 h5.08
  text "8. Silkscreen: Apply silkscreen artwork to the top and bottom sides of the" at 349.935,107.4 h5.08
  text "board using non-conductive epoxy ink. Silkscreen color: YELLOW" at 365.175,97.24 h5.08
  text "9. Solder mask: Liquid photo imageable solder mask over bare copper (SMOBC)" at 349.935,87.08 h5.08
  text "Color: GREEN" at 365.175,76.92 h5.08
  text "CUT OUT" at 45.695,72.644 h1.25
  text "CUT OUT" at 1.27,72.593 h1.25
  text "CUT OUT" at 153.492,72.593 h1.25
  text "CUT OUT" at 254.356,72.593 h1.25
  text "10. Gerber file format: 274-X with 4/3 accuracy (XXXX.XXX). Gerber files are" at 349.935,66.76 h5.08
  text "CUT OUT" at 101.981,63.754 h1.25 r90
  text "CUT OUT" at 204.394,63.703 h1.25 r90
  text "CUT OUT" at 306.908,63.043 h1.25 r90
  text "B" at -73.685,60.915 h1.78
  text "B" at 731.495,60.915 h1.78
  text "in mm, NC Drill files in mils with 2/4 accuracy." at 365.175,56.6 h5.08
  text "11. Maximum warp and twist not to exceed .254mm per linear 25.4mm." at 349.935,46.44 h5.08
  text "CUT OUT" at 68.732,39.522 h1.5
  text "12. Vendor UL flame code 94V-0 to be clearly marked on the silkscreen layer" at 349.935,36.28 h5.08
  text "CUT OUT" at 204.445,31.521 h1.25 r90
  text "CUT OUT" at -0.66,30.734 h1.25 r90
  text "CUT OUT" at 306.934,28.245 h1.25 r90
  text "CUT OUT" at 101.981,27.584 h1.25 r90
  text "only." at 369.25,26.625 h5.08
  text "13. Panelization: 3x1 array, step 102.5mm." at 350.185,15.995 h5.08
  text "14. All boards to be 100% electrically tested." at 350.185,5.835 h5.08
  text "CUT OUT" at 25.248,-2.616 h1.5
  text "CUT OUT" at 107.823,-2.718 h1.5
  text "CUT OUT" at 213.639,-2.896 h1.5
  text "CUT OUT" at 286.233,-2.896 h1.5
  text "15. Unused inner layer pads may be removed." at 350.185,-4.325 h5.08
  text "16. Copper thieving is NOT allowed on the PCB." at 350.685,-15.27 h5.08
  text "17. All drilled holes are specified as finished hole size." at 350.685,-25.43 h5.08
  text "18. Via holes .010 and smaller may be plated shut - All other plated holes" at 350.685,-35.59 h5.08
  text "have a +/- 0.003 inch tolerance." at 365.925,-45.75 h5.08
  text "Non-plated =/- 0.0015 unless otherwise specified." at 365.925,-55.91 h5.08
  text "19. Finished board thickness 0.062 =/-0.006 inch tolerance" at 350.685,-66.07 h5.08
  text "C" at -73.685,-66.085 h1.78
  text "C" at 731.495,-66.085 h1.78
  text "20. Slot/Cutout tolerance +/- 0.005." at 350.625,-77.75 h5.08
  text "21. IMPEDANCE CONTROLLED LINES ARE ON TOP SIDE (L1), L3, L8, L10, &" at 350.125,-87.75 h5.08
  text "BOTTOM SIDE (L12)" at 368.625,-96.5 h5.08
  text "100 OHM DIFFERENTIAL PAIR EXTERNAL = .122mm LINE/.125mm SPACE" at 365.075,-104.775 h5.08
  text "100 OHM DIFFERENTIAL PAIR INTERNAL = .101mm LINE/.200mm SPACE" at 365.075,-113.775 h5.08
  text "50 OHM SINGLE ENDED EXTERNAL = .200mm LINE" at 367.575,-123.775 h5.08
  text "50 OHM SINGLE ENDED INTERNAL = .104mm LINE" at 367.575,-133.275 h5.08
  text "22. IMPEDANCE CONTROLLED LINES ARE ON TOP SIDE (L1), L3, L10, & L12." at 350.675,-143.6 h5.08
  text "90 OHM DIFFERENTIAL PAIR EXTERNAL = .155mm LINE/.125mm SPACE" at 368.375,-153.75 h5.08
  text "90 OHM DIFFERENTIAL PAIR INTERNAL = .103mm LINE/.125mm SPACE" at 368.375,-162.75 h5.08
  text "23. IMPEDANCE CONTROLLED LINES ARE ON TOP SIDE (L1), L8, & L12." at 352.325,-172.325 h5.08
  text "85 OHM DIFFERENTIAL PAIR EXTERNAL = .175mm LINE/.125mm SPACE" at 368.925,-180.575 h5.08
  text "85 OHM DIFFERENTIAL PAIR INTERNAL = .119mm LINE/.125mm SPACE" at 368.925,-190.075 h5.08
  text "D" at -73.685,-193.085 h1.78
  text "D" at 731.495,-193.085 h1.78
  text "24. Class 2 annular ring is acceptable on .2mm vias with .45mm pad." at 350.975,-198.75 h5.08
  text "25. Vendor to generate netlist from Gerber data." at 351.525,-209.825 h5.08
  text "ENGINEER:" at 615.29,-218.79 h1.14
  text "TITLE:" at 653.39,-218.79 h1.14
  text "Digi" at 683.5,-221.25 h3.17
  text "Daniel Alesanco" at 616.56,-222.346 h1.78
  text "PCB DESIGNER:" at 615.29,-226.283 h1.14
  text "i.MX6x SBC" at 674.375,-228 h3.17
  text "Mark Larson" at 616.56,-229.458 h1.78
  text "DATE:" at 615.29,-234.03 h1.14
  text "PART NO.:" at 653.39,-234.03 h1.14
  text "REV:" at 706.73,-234.03 h1.14
  text "30014752-01" at 672.25,-236.25 h1.78
  text "B" at 718.5,-236.25 h1.78
  text ".Print_Date" at 616.56,-237.078 h1.78
  text "FILE NAME:" at 615.29,-241.65 h1.14
  text "SVN HEAD REV:" at 653.39,-241.65 h1.14
  text "SCALE:" at 706.73,-241.65 h1.14
  text "110 N 5th St.  Suite 400" at 580.365,-242.285 h1.78
  text ".VersionControl_RevNumber" at 668.376,-243.682 h1.78
  text ".PCB_FILE_NAME_NO_PATH" at 616.56,-244.698 h1.78
  text "Minneapolis MN 55403" at 580.365,-245.46 h1.78
  text "1" at -26.517,-251.429 h1.78
  text "2" at 74.956,-251.429 h1.78
  text "3" at 176.429,-251.429 h1.78
  text "4" at 278.054,-251.429 h1.78
  text "5" at 379.612,-251.429 h1.78
  text "6" at 481.17,-251.429 h1.78
  text "7" at 582.812,-251.429 h1.78
  text "8" at 684.285,-251.429 h1.78
Drill Drawing:
  text ".Layer_Name" at 35.736,-19.262 h2.54
  text ".Legend" at -10.625,-197.125 h2.54

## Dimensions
0,72 to 100,72 on Sheet Graphics
0,72 to 102.5,72 on Sheet Graphics
202.5,72 to 205,72 on Sheet Graphics
0,72 to 0,0 on Sheet Graphics
-15,79.5 to 0,72 on Sheet Graphics
-15,79.5 to 320,79.5 on Sheet Graphics
-15,79.5 to -15,-11.5 on Sheet Graphics
-15,-11.5 to 0,0 on Sheet Graphics
305,0 to 306.25,-4 on Sheet Graphics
